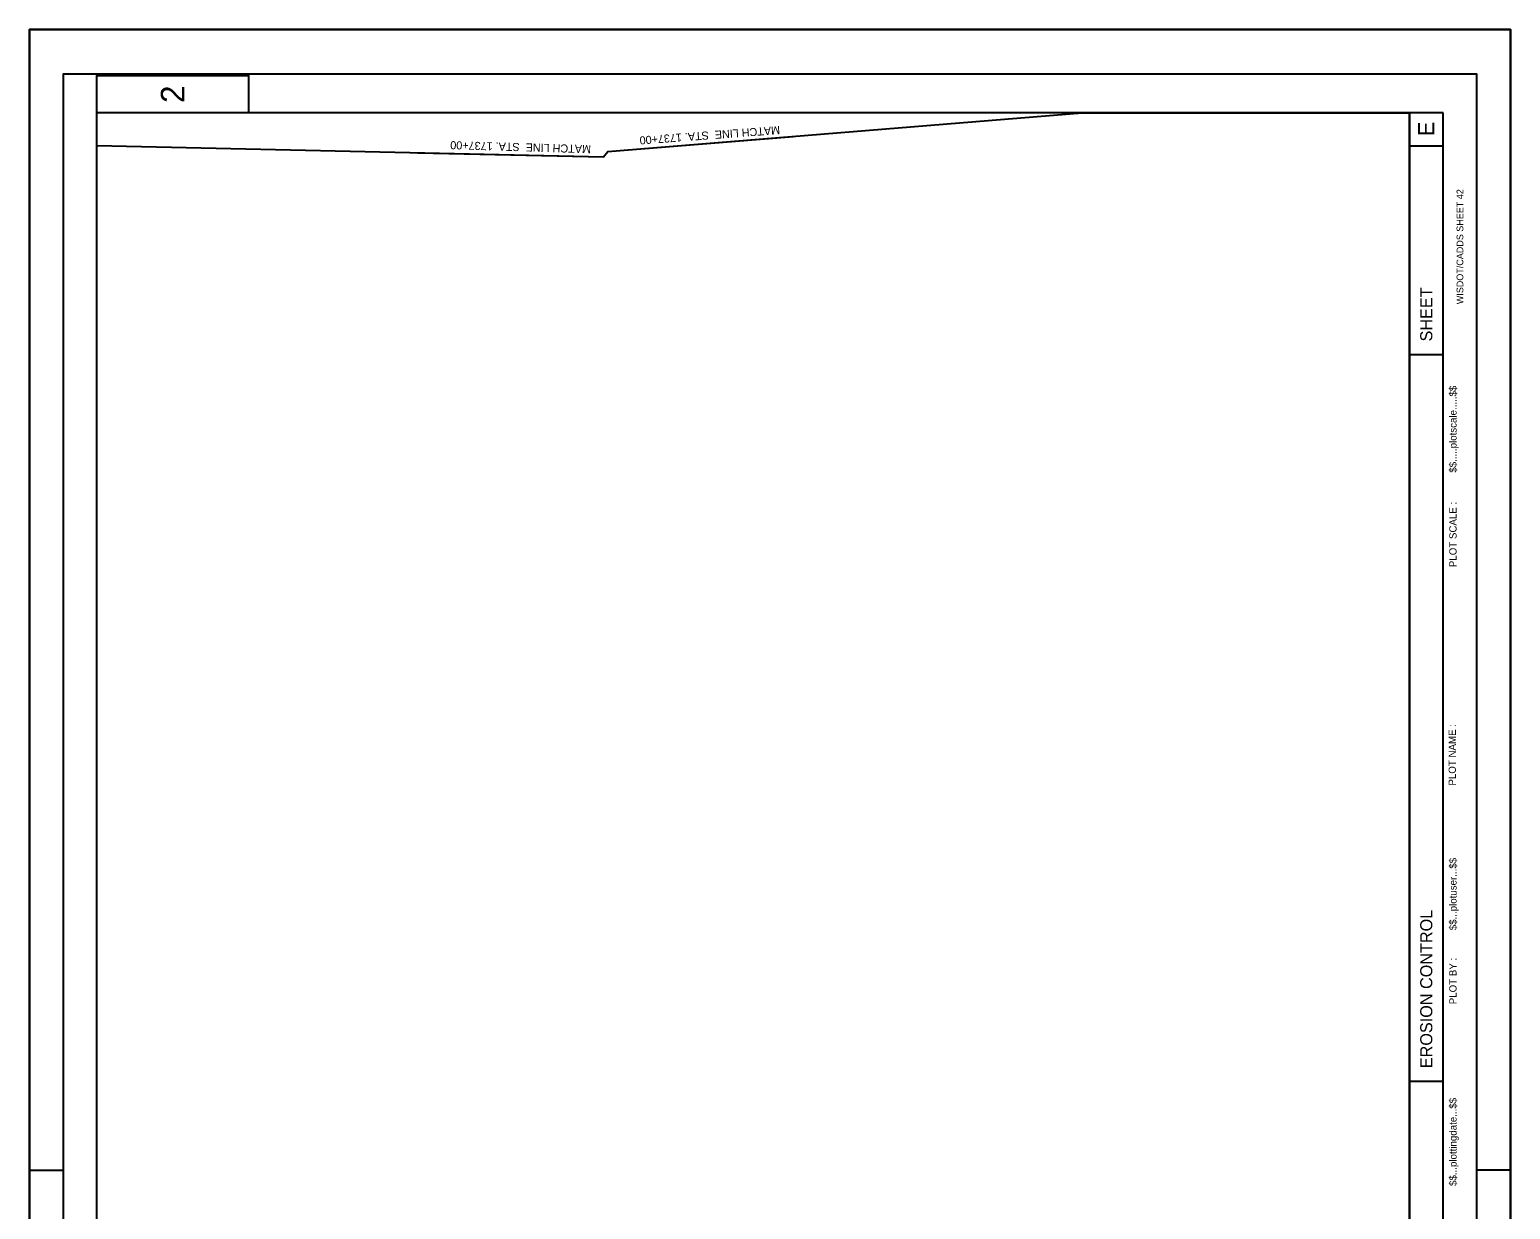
# Model space of a CAD drawing. Extents: x 361080 to 362180, y 131293 to 132993.
# Drawn here: x 361080 to 362180, y 132116 to 132993 of the extents above; entities that cross this region are included whole.
import ezdxf

# ---------------------------------------------------------------- set-up
doc = ezdxf.new("R2010")
doc.units = 0
for name, color, linetype in [('Default', 7, 'Continuous'), ('P_SHTIDX_2 [KAPUR_CADDS_LEVELS]', 7, 'Continuous'), ('P_SHTIDX_3 [KAPUR_CADDS_LEVELS]', 7, 'Continuous'), ('P_SHTIDX_4 [KAPUR_CADDS_LEVELS]', 7, 'Continuous'), ('P_TXT_Plan 2 [KAPUR_CADDS_LEVELS]', 7, 'Continuous'), ('P_TXT_Plan 3 [KAPUR_CADDS_LEVELS]', 7, 'Continuous'), ('P_TXT_Plan 4 [KAPUR_CADDS_LEVELS]', 7, 'Continuous')]:
    doc.layers.add(name, color=color, linetype=linetype)

msp = doc.modelspace()

# ---------------------------------------------------------------- linework, layer by layer
at = {"layer": 'Default'}
msp.add_lwpolyline([(362105.1, 131446.1), (361588.3, 131403.7), (361490.1, 131398.9), (361130.1, 131405.5), (361130.1, 132906.6), (361506.5, 132898.2), (361509.7, 132902.2), (361861.9, 132931.1), (362105.1, 132931.1)], close=True, dxfattribs=at)
msp.add_lwpolyline([(362105.1, 131446.1), (361588.3, 131403.7), (361490.1, 131398.9), (361130.1, 131405.5), (361130.1, 132906.6), (361506.5, 132898.2), (361509.7, 132902.2), (361861.9, 132931.1), (362105.1, 132931.1)], close=True, dxfattribs=at)
msp.add_lwpolyline([(362105.1, 131446.1), (361588.3, 131403.7), (361490.1, 131398.9), (361130.1, 131405.5), (361130.1, 132906.6), (361506.5, 132898.2), (361509.7, 132902.2), (361861.9, 132931.1), (362105.1, 132931.1)], close=True, dxfattribs=at)
msp.add_lwpolyline([(362105.1, 131446.1), (361588.3, 131403.7), (361490.1, 131398.9), (361130.1, 131405.5), (361130.1, 132906.6), (361506.5, 132898.2), (361509.7, 132902.2), (361861.9, 132931.1), (362105.1, 132931.1)], close=True, dxfattribs=at)
msp.add_lwpolyline([(362105.1, 131446.1), (361588.3, 131403.7), (361490.1, 131398.9), (361130.1, 131405.5), (361130.1, 132906.6), (361506.5, 132898.2), (361509.7, 132902.2), (361861.9, 132931.1), (362105.1, 132931.1)], close=True, dxfattribs=at)
msp.add_lwpolyline([(362105.1, 131446.1), (361588.3, 131403.7), (361490.1, 131398.9), (361130.1, 131405.5), (361130.1, 132906.6), (361506.5, 132898.2), (361509.7, 132902.2), (361861.9, 132931.1), (362105.1, 132931.1)], close=True, dxfattribs=at)
msp.add_lwpolyline([(362105.1, 131446.1), (361588.3, 131403.7), (361490.1, 131398.9), (361130.1, 131405.5), (361130.1, 132906.6), (361506.5, 132898.2), (361509.7, 132902.2), (361861.9, 132931.1), (362105.1, 132931.1)], close=True, dxfattribs=at)
msp.add_lwpolyline([(362105.1, 131446.1), (361588.3, 131403.7), (361490.1, 131398.9), (361130.1, 131405.5), (361130.1, 132906.6), (361506.5, 132898.2), (361509.7, 132902.2), (361861.9, 132931.1), (362105.1, 132931.1)], close=True, dxfattribs=at)
at = {"layer": 'P_SHTIDX_2 [KAPUR_CADDS_LEVELS]'}
msp.add_lwpolyline([(361080.1, 131292.8), (361080.1, 132992.8), (362180.1, 132992.8), (362180.1, 131292.8), (361080.1, 131292.8)], dxfattribs=at)
at = {"layer": 'P_SHTIDX_3 [KAPUR_CADDS_LEVELS]'}
for p, q in [((361130.1, 132992.8), (361080.1, 132992.8)), ((361080.1, 132942.8), (361080.1, 132992.8)), ((362180.1, 132992.8), (362130.1, 132992.8)), ((362180.1, 132942.8), (362180.1, 132992.8)), ((361130.1, 131356.1), (361130.1, 132931.1)), ((362130.1, 132931.1), (361130.1, 132931.1)), ((362105.1, 131356.1), (362105.1, 132931.1)), ((362130.1, 131356.1), (362130.1, 132931.1)), ((362130.1, 132906.1), (362105.1, 132906.1)), ((362130.1, 132751.1), (362105.1, 132751.1)), ((362130.1, 132211.1), (362105.1, 132211.1)), ((361080.1, 132120.3), (361080.1, 132170.3)), ((362180.1, 132120.3), (362180.1, 132170.3)), ((361080.1, 132145.3), (361105.1, 132145.3)), ((362180.1, 132145.3), (362155.1, 132145.3))]:
    msp.add_line(p, q, dxfattribs=at)
msp.add_lwpolyline([(361130.1, 132931.1), (361130.1, 132958.6), (361242.6, 132958.6), (361242.6, 132931.1)], close=True, dxfattribs=at)
at = {"layer": 'P_SHTIDX_4 [KAPUR_CADDS_LEVELS]'}
for points in [[(362180.1, 131292.8), (362180.1, 132992.8), (361080.1, 132992.8), (361080.1, 131292.8)], [(362155.1, 131304.8), (362155.1, 132959.8), (361105.1, 132959.8), (361105.1, 131304.8)]]:
    msp.add_lwpolyline(points, close=True, dxfattribs=at)
at = {"layer": 'P_TXT_Plan 3 [KAPUR_CADDS_LEVELS]'}
for p, q in [((361509.7, 132902.2), (361647.4, 132913.5)), ((361368.4, 132901.3), (361506.5, 132898.2))]:
    msp.add_line(p, q, dxfattribs=at)
at = {"layer": 'P_TXT_Plan 4 [KAPUR_CADDS_LEVELS]'}
msp.add_lwpolyline([(361080.1, 131292.8), (361080.1, 132992.8), (362180.1, 132992.8), (362180.1, 131292.8)], close=True, dxfattribs=at)

# ---------------------------------------------------------------- texts
at = {"layer": 'P_SHTIDX_3 [KAPUR_CADDS_LEVELS]'}
for s, height, p in [('2', 17.5, (361195.1, 132938.3)), ('E', 12, (362123.5, 132913.7)), ('WISDOT/CADDS SHEET 42', 5, (362145.1, 132788.8)), ('SHEET ', 9, (362122.1, 132761.1)), ('$$.....plotscale.....$$', 5.4, (362140.1, 132663.6)), ('PLOT SCALE : ', 5.4, (362140.1, 132593.4)), ('PLOT NAME :                      ', 5.4, (362139.6, 132431.1)), ('$$...plotuser...$$', 5.4, (362140.1, 132323.6)), ('EROSION CONTROL', 9, (362122.1, 132221.1)), ('PLOT BY :', 5.4, (362140.1, 132268.6)), ('$$...plottingdate...$$', 5.4, (362140.1, 132133.6))]:
    msp.add_text(s, height=height, rotation=90, dxfattribs=at).set_placement(p)
at = {"layer": 'P_TXT_Plan 2 [KAPUR_CADDS_LEVELS]'}
for rotation, p in [(184.2781, (361637.3, 132921.2)), (178.3028, (361497.2, 132906.9))]:
    msp.add_text('MATCH LINE  STA. 1737+00', height=6, rotation=rotation, dxfattribs=at).set_placement(p)

doc.saveas('drawing.dxf')
